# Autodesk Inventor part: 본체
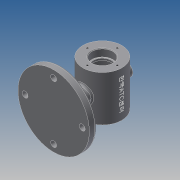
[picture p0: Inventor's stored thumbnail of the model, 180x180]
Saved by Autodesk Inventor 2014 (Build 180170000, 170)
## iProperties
Created: 2018-12
Part Number: 본체
Material: Generic
Document SubType Name: Modeling
Designer: kb542-13
Density: 1 g/cm^3
Appearance: Default
Author: kb542-13
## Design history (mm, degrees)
sketch "스케치1"
  geometry: C1 r 30 at (0, 0); 1 further point
  constraints: 1 centre point, 1 coincident
  dimensions: "d0" = 60 diameter of C1
extrude "돌출1" new body sketch "스케치1" stored distance "d1" = 70; taper "d2" = 0 deg
sketch "스케치2"
  geometry: L1 (30, 35)-(-30, 35) reference; L2 (0, 35)-(0, -35); L3 (-30, -35)-(30, -35) reference; L4 (16, 35)-(16, 23); L5 (16, 23)-(14, 23); L6 (14, 23)-(14, 20); L7 (14, 20)-(25, 20); L8 (25, 20)-(25, -20); L9 (25, -20)-(14, -20); L10 (14, -20)-(14, -23); L11 (14, -23)-(16, -23); L12 (16, -23)-(16, -35); L13 (16, 35)-(0, 35); L14 (16, -35)-(0, -35); 1 further point
  constraints: 24 end point, 6 parallel, 3 perpendicular, 2 collinear, 2 midpoint, 2 point on line
  dimensions: "d3" = 32 diameter of L4 L2; "d4" = 3 distance of L5.end L6.end; "d5" = 3 distance of L9.end L10.end; "d6" = 50 diameter of L8 L2; "d7" = 40 distance of L7.end L8.end; "d8" = 12 distance of L4.start L4.end; "d9" = 32 diameter of L12 L2; "d10" = 28 diameter of L10 L2; "d11" = 28 diameter of L6 L2
revolve "회전1" sketch "스케치2" stored, may be unused: angle "d12" = 90 deg
node "작업 평면1"
sketch "스케치5"
  geometry: L1 (-30, -35)-(-30, 35) reference; L2 (-30, 0)-(-75, 0); L3 (-75, 0)-(-75, 55); L4 (-75, 55)-(-64, 55); L5 (-64, 55)-(-49.263, 0); 1 further point
  constraints: 8 end point, 2 perpendicular, 1 midpoint, 1 parallel, 1 point on line
  dimensions: "d27" = 75 distance from line of point (0, 0) L3; "d28" = 11 distance of L3.end L4.end; "d29" = 75 deg angle of L5 L4; "d30" = 110 diameter of L4 L2
revolve "회전3" sketch "스케치5" stored, may be unused: angle "d31" = 90 deg
node "작업 평면2"
sketch "스케치6"
  geometry: C1 r 12 at (0, 0); 1 further point
  constraints: 1 centre point, 1 coincident
  dimensions: "d33" = 24 diameter of C1
extrude "돌출2" join sketch "스케치6" stored distance "d34" = 11; taper "d35" = 0 deg
node "작업 평면3"
sketch "스케치8"
  geometry: C1 r 4.5 at (0, 44); 1 further point
  constraints: 1 centre point, 1 vertical alignment
  dimensions: "d37" = 44 distance of point (0, 0) C1.centre; "d38" = 9 diameter of C1
extrude "돌출3" cut sketch "스케치8" distance "d39" = 11; taper "d40" = 0 deg
sketch "스케치9"
  geometry: C1 r 4.5 at (0, 44) reference; C2 r 7 at (0, 44); 1 further point
  constraints: 1 centre point, 1 coincident
  dimensions: "d44" = 14 diameter of C2
extrude "돌출4" cut sketch "스케치9" stored distance "d45" = 11; taper "d46" = 0 deg
sketch "스케치10"
  geometry: C1 r 16 at (0, 0) reference; 1 further point
  constraints: 1 vertical alignment
  dimensions: "d50" = 23 distance of C1.centre point (0, 23)
hole "구멍1" sketch "스케치10" at (0, 23) diameter "d51" = 3.242; stored, may be unused: countersink angle "d55" = 90 deg, drill point angle "d57" = 118 deg; dims "d52" = 8, "d53" = 4, "d54" = 2, "d56" = 10
node "작업 평면4"
sketch "스케치11"
  geometry: C1 r 10 at (0, 0); 1 further point
  constraints: 1 centre point, 1 coincident
  dimensions: "d62" = 20 diameter of C1
extrude "돌출5" join sketch "스케치11" stored distance "d63" = 11; taper "d64" = 0 deg
sketch "스케치12"
  geometry: C1 r 10 at (0, 0) reference; C2 r 5 at (0, 0)
  constraints: 1 centre point, 1 coincident
  dimensions: "d65" = 10 diameter of C2
extrude "돌출6" cut sketch "스케치12" stored distance "d66" = 11; taper "d67" = 0 deg
fillet "모깎기1" dims "d68" = 0.3
fillet "모깎기2" dims "d69" = 0.3
fillet "모깎기3" dims "d70" = 3
node "작업 평면5"
sketch "스케치14"
  geometry: L1 (30, 35)-(-30, 35) reference; L2 (30, -35)-(30, 35) reference; 2 further points
  constraints: 1 other
  dimensions: "d72" = 30 distance from line of L2 point (0, 0); "d73" = 35 distance from line of point (0, 0) L1
feature "엠보싱1" sketch "스케치14" dims "d2" = 0, "d74" = 0.5, "d75" = 0
chamfer "모따기1" distance "d76" = 1; stored, may be unused: second distance "d77" = 2, angle "d78" = 45 deg
chamfer "모따기2" distance "d79" = 1; stored, may be unused: second distance "d80" = 2, angle "d81" = 45 deg
fillet "모깎기4" dims "d82" = 3
node "솔리드1"
pattern_circular "원형 패턴1" dims angle "d42" = 360 deg
pattern_circular "원형 패턴2" dims angle "d48" = 360 deg
pattern_circular "원형 패턴3" dims angle "d59" = 360 deg
mirror "대칭1"
other parameters: "d13" = -75, "d61" = -112, "d71" = 58.75
